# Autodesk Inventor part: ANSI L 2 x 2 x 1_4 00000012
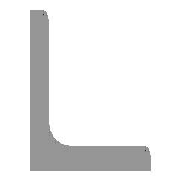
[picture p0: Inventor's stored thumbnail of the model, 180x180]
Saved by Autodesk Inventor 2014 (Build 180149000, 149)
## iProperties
IsCustomPart: 1
Created: 2007-02
Part Number: ANSI L 2 x 2 x 1_4 00000012
Material: Steel, Mild
Document SubType Name: Modeling
Standard: AISC
Designer: Autodesk, Inc.
Size Designation: L 2 x 2 x 1/4
Stock Number: L 2 x 2 x 1/4
Density: 7.86 g/cm^3
Description: Angle Steel
Standards Organization: ANSI
Language: en-US
Categories: <MemberInstance><Categories><Category DisplayName="Structural Shapes" InternalName="089c4875-fa83-4c05-b084-43b9cc11f5ed" Mnemonic="GRDR"><CategoryParameter Dis
Mass: 5016.03 g
Surface Area: 2083.72 cm^2
Volume: 638.172 cm^3
Appearance: Steel
_FrameMemberDoc: Frame Member File
_Version: 13.0.0
_CCFamilyMember: 11
_CCFamilyDisplayName: ANSI L (Equal angles) - Angle Steel
G_L: 41.250 in
G_W: 2.000 in
G_H: 2.000 in
+CF352427-B6DD-4A7B-8774-4A21CA8D84D1+CUTDETAIL2: Cut
+AB975018-38CB-4017-B372-74A5C2C524EF+CUTDETAIL3: Notch
Author: Autodesk, Inc.
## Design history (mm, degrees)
node "Start plane"
node "End plane"
sketch "Sketch"
  geometry: L1 (50.8, 0)-(0, 0); L2 (0, 0)-(0, 50.8); L3 (0, 50.8)-(3.302, 50.8); L4 (6.35, 47.752)-(6.35, 12.7); L5 (12.7, 6.35)-(47.752, 6.35); L6 (50.8, 3.302)-(50.8, 0); L7 (0, -11.041)-(0, 31.538); L8 (-11.041, 0)-(31.538, 0); L9 (0, 63.926)-(0, -23.536) reference; L10 (-23.536, 0)-(63.926, 0) reference; A1 r 6.35 centre (12.7, 12.7) between (6.35, 12.7) and (12.7, 6.35); A2 r 3.048 centre (3.302, 47.752) between (6.35, 47.752) and (3.302, 50.8); A3 r 3.048 centre (47.752, 3.302) between (50.8, 3.302) and (47.752, 6.35); 3 further points
  constraints: 16 end point, 6 point on circle, 6 point on line, 6 tangent, 4 parallel, 3 centre point, 2 collinear, 1 equal radius, 1 horizontal, 1 perpendicular
  dimensions: "d0" = 50.8 distance between parallel lines of L6 L2 (= G_H); "d1" = 50.8 distance between parallel lines of L3 L1 (= G_H); "d2" = 6.35 distance between parallel lines of L2 L4 (= G_T); "d3" = 6.35 distance between parallel lines of L1 L5 (= G_T); "d10" = 0 distance between parallel lines of L7 L2 (computed from ex); "d11" = 0 distance between parallel lines of L8 L1 (computed from d10); "d14" = 6.35 radius of A1 (= G_IR); "d15" = 3.048 radius of A2 (= G_ER)
extrude "Body" new body sketch "Sketch" stored distance "d4" = 1047.75 (= G_L); taper "d5" = 0 deg
node "Driven Length"
  sketch "Sketch5"
    geometry: L1 (0, 0)-(10, 0) reference
    constraints: 2 end point, 1 horizontal
  workplane "Work Plane8"
  sketch "Sketch6"
    geometry: L1 (-2, 0)-(12, 0) reference; L2 (-2, 1047.75)-(12, 1047.75) reference
    dimensions: "d21" = 1047.75 distance between parallel lines of L1 L2 (derived)
workplane "Work Plane5"
split "Split1"
workplane "Work Plane6"
workplane "Work Plane7"
derived "ANSI L 2 x 2 x 1_4 00000007.ipt"
  sketch "Sketch_2"
    geometry: L1 (50.8, 0)-(0, 0) reference; L2 (0, 0)-(0, 50.8) reference; L3 (0, 50.8)-(3.302, 50.8) reference; L4 (6.35, 47.752)-(6.35, 12.7) reference; L5 (12.7, 6.35)-(47.752, 6.35) reference; L6 (50.8, 3.302)-(50.8, 0) reference; L7 (0, -11.041)-(0, 31.538) reference; L8 (-11.041, 0)-(31.538, 0) reference; L9 (0, 63.926)-(0, -23.536) reference; L10 (-23.536, 0)-(63.926, 0) reference; A1 r 6.35 centre (12.7, 12.7) between (6.35, 12.7) and (12.7, 6.35) reference; A2 r 3.048 centre (3.302, 47.752) between (6.35, 47.752) and (3.302, 50.8) reference; A3 r 3.048 centre (47.752, 3.302) between (50.8, 3.302) and (47.752, 6.35) reference; 3 further points
extrude "Extrusion3" cut sketch "Sketch_2" stored distance "d18" = 3.302; taper "d19" = 0 deg
body "Solid1"
other parameters: "G_H" = 50.8 [user parameter; used in 2 equation terms], "G_T" = 6.35 [user parameter; used in 2 equation terms], "G_ER" = 3.048 [user parameter; used in 1 equation term], "G_IR" = 6.35 [user parameter; used in 1 equation term], "G_L" = 1047.75 (= d21) [user parameter; used in 1 equation term], "ex" = 0 [user parameter; used in 1 equation term], "G_OFFSET_START" = 0 [user parameter; used in 1 equation term], "G_OFFSET_END" = -6.35 [user parameter; used in 1 equation term], "d12" = 0 (computed from G_OFFSET_START), "d13" = 1047.75 (= G_OFFSET_END + B_L), "B_L" = 1054.1 [user parameter; used in 1 equation term], "d20" = 90 deg
